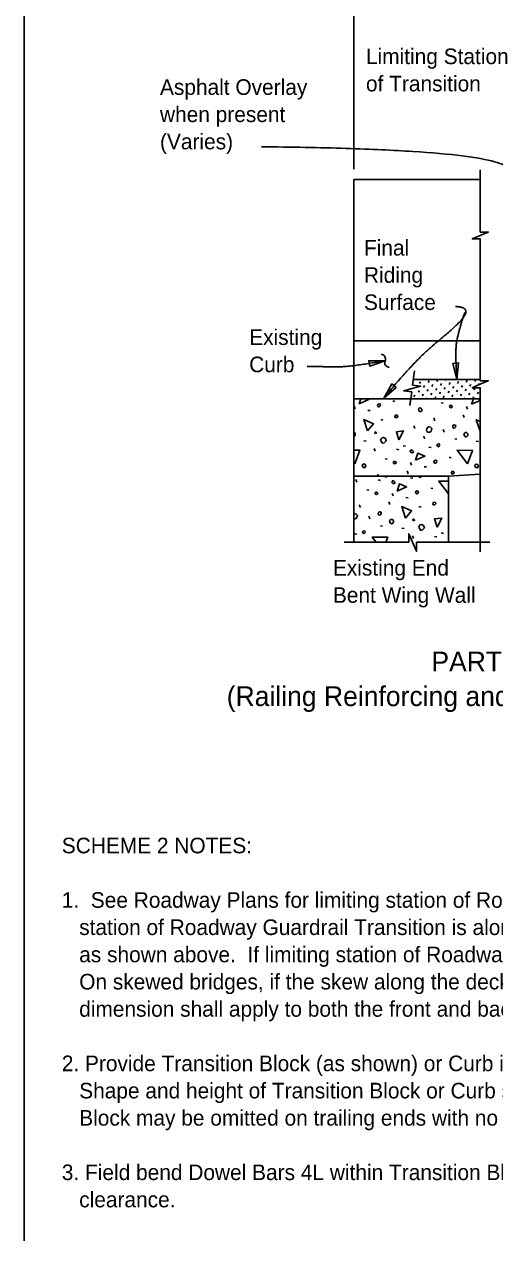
# Model space of a CAD drawing. Extents: x 1 to 39.2, y 0 to 26.
# Drawn here: x 20.53 to 26.61, y 0 to 15.72 of the extents above; entities that cross this region are included whole.
import ezdxf

# ---------------------------------------------------------------- set-up
doc = ezdxf.new("R2010")
doc.units = 0
for name, color, linetype in [('Dimension', 7, 'Continuous'), ('Miscellaneous', 7, 'Continuous'), ('TrafBarrierConc', 7, 'Continuous')]:
    doc.layers.add(name, color=color, linetype=linetype)

msp = doc.modelspace()

# ---------------------------------------------------------------- linework, layer by layer
at = {"layer": 'Dimension'}
for p, q in [((20.533, 25.97), (20.533, 0)), ((24.79, 19.042), (24.789, 13.85))]:
    msp.add_line(p, q, dxfattribs=at)
for points in [[(26.42, 12.096), (26.42, 12.948), (26.317, 12.948), (26.42, 12.993), (26.524, 13.038), (26.42, 13.038), (26.42, 13.841)], [(26.42, 8.903), (26.42, 11.026), (26.317, 11.026), (26.42, 11.071), (26.524, 11.116), (26.42, 11.116), (26.42, 12.096)], [(25.513, 10.797), (25.536, 10.971), (25.433, 10.984), (25.542, 11.015), (25.65, 11.046), (25.548, 11.06), (25.572, 11.242)], [(26.545, 9.028), (25.598, 9.028), (25.598, 8.912), (25.498, 9.137), (25.498, 9.028), (24.665, 9.028)]]:
    msp.add_lwpolyline(points, dxfattribs=at)
for points in [[(25.193, 11.373), (24.981, 11.373), (24.993, 11.304)], [(26.12, 11.135), (26.14, 11.345), (26.069, 11.34)], [(25.174, 10.89), (25.333, 11.029), (25.278, 11.074)]]:
    msp.add_lwpolyline(points, close=True, dxfattribs=at)
for centre, start, end in [((25.138, 11.398), 336.0025, 87.7297), ((25.247, 11.35), 156.0025, 267.7297)]:
    msp.add_arc(centre, 0.0596, start, end, dxfattribs=at)
for points in [[(23.597, 14.141), (26.772, 14.106), (26.847, 13.542), (26.922, 12.078), (27.461, 11.132)], [(26.101, 12.075), (26.22, 12.069), (26.245, 11.981), (26.101, 11.812), (25.569, 11.373), (25.174, 10.89)], [(26.221, 11.999), (26.114, 11.68), (26.101, 11.386), (26.12, 11.135)], [(24.184, 11.298), (24.459, 11.298), (24.71, 11.292), (25.193, 11.373)]]:
    msp.add_open_spline(points, degree=2, dxfattribs=at)
at = {"layer": 'Miscellaneous'}
for p, q in [((25.588, 11.127), (25.592, 11.133)), ((25.637, 11.079), (25.65, 11.101)), ((25.686, 11.03), (25.699, 11.052)), ((25.748, 11.092), (25.761, 11.114)), ((25.797, 11.043), (25.81, 11.065)), ((25.846, 10.994), (25.859, 11.016)), ((25.859, 11.104), (25.872, 11.127)), ((25.907, 11.056), (25.92, 11.078)), ((25.956, 11.007), (25.969, 11.029)), ((25.969, 11.117), (25.978, 11.133)), ((26.018, 11.069), (26.031, 11.091)), ((26.067, 11.02), (26.08, 11.042)), ((26.08, 11.13), (26.081, 11.133)), ((26.129, 11.082), (26.142, 11.104)), ((26.177, 11.033), (26.19, 11.055)), ((26.226, 10.984), (26.239, 11.006)), ((26.239, 11.095), (26.252, 11.117)), ((26.288, 11.046), (26.301, 11.068)), ((26.337, 10.997), (26.35, 11.019)), ((26.35, 11.107), (26.363, 11.13)), ((26.399, 11.059), (26.412, 11.081)), ((25.292, 10.855), (25.318, 10.849)), ((25.563, 10.906), (25.575, 10.929)), ((25.624, 10.968), (25.637, 10.99)), ((25.673, 10.919), (25.686, 10.941)), ((25.728, 10.88), (25.735, 10.893)), ((25.735, 10.981), (25.748, 11.003)), ((25.784, 10.932), (25.797, 10.954)), ((25.833, 10.883), (25.846, 10.906)), ((25.894, 10.945), (25.907, 10.967)), ((25.943, 10.896), (25.956, 10.919)), ((26.005, 10.958), (26.018, 10.98)), ((26.054, 10.909), (26.067, 10.932)), ((26.116, 10.971), (26.129, 10.993)), ((26.165, 10.922), (26.177, 10.944)), ((26.217, 10.88), (26.226, 10.896)), ((26.275, 10.935), (26.288, 10.957)), ((26.324, 10.886), (26.337, 10.909)), ((26.386, 10.948), (26.399, 10.97)), ((24.804, 10.752), (24.791, 10.786)), ((24.968, 10.733), (25, 10.729)), ((25.917, 10.83), (25.944, 10.825)), ((26.257, 10.749), (26.244, 10.782)), ((25.136, 10.614), (25.164, 10.607)), ((25.834, 10.598), (25.82, 10.634)), ((26.214, 10.639), (26.2, 10.674)), ((25.578, 10.498), (25.564, 10.533)), ((25.703, 10.365), (25.691, 10.399)), ((25.956, 10.452), (25.942, 10.487)), ((24.917, 10.338), (24.947, 10.333)), ((25.065, 10.204), (25.053, 10.238)), ((25.339, 10.231), (25.368, 10.224)), ((25.426, 10.275), (25.454, 10.268)), ((25.756, 10.259), (25.787, 10.254)), ((26.094, 10.363), (26.119, 10.36)), ((26.37, 10.335), (26.4, 10.33)), ((25.193, 10.105), (25.219, 10.1)), ((26.02, 10.126), (26.046, 10.121)), ((25.106, 9.883), (25.095, 9.909)), ((25.49, 9.914), (25.475, 9.95)), ((25.532, 10.024), (25.52, 10.057)), ((25.696, 10.004), (25.728, 10.001)), ((24.829, 9.806), (24.816, 9.84)), ((25.103, 9.833), (25.131, 9.825)), ((25.189, 9.877), (25.218, 9.87)), ((25.52, 9.861), (25.55, 9.856)), ((25.864, 9.886), (25.876, 9.883)), ((24.956, 9.707), (24.982, 9.702)), ((25.295, 9.626), (25.283, 9.659)), ((25.46, 9.606), (25.492, 9.603)), ((25.783, 9.728), (25.81, 9.723)), ((24.873, 9.475), (24.859, 9.511)), ((25.253, 9.516), (25.239, 9.551)), ((25.628, 9.488), (25.656, 9.481)), ((24.995, 9.329), (24.981, 9.364)), ((24.795, 9.136), (24.825, 9.131)), ((25.133, 9.24), (25.157, 9.237)), ((25.408, 9.212), (25.439, 9.207)), ((25.918, 9.148), (25.946, 9.141)), ((25.557, 9.078), (25.545, 9.111)), ((25.831, 9.104), (25.859, 9.097))]:
    msp.add_line(p, q, dxfattribs=at)
for points in [[(24.857, 10.816), (24.877, 10.883)], [(24.947, 10.883), (24.979, 10.871), (24.857, 10.816)], [(26.31, 10.812), (26.332, 10.883)], [(26.42, 10.862), (26.31, 10.812)], [(26.392, 10.883), (26.42, 10.872)], [(25.104, 10.78), (25.111, 10.78), (25.125, 10.788), (25.131, 10.803), (25.129, 10.812), (25.115, 10.819), (25.097, 10.809), (25.094, 10.798), (25.097, 10.788), (25.104, 10.78)], [(25.626, 10.736), (25.634, 10.72), (25.656, 10.717), (25.665, 10.733), (25.668, 10.747), (25.659, 10.756), (25.643, 10.765), (25.627, 10.759), (25.622, 10.743), (25.626, 10.736)], [(26.025, 10.772), (26.045, 10.766), (26.057, 10.775), (26.059, 10.788), (26.055, 10.791), (26.041, 10.798), (26.029, 10.796), (26.027, 10.784), (26.025, 10.772)], [(24.965, 10.468), (24.917, 10.614), (25.042, 10.559), (24.965, 10.468)], [(25.323, 10.639), (25.345, 10.639), (25.355, 10.65), (25.35, 10.669), (25.327, 10.671), (25.323, 10.66), (25.318, 10.651), (25.323, 10.639), (25.32, 10.643)], [(26.066, 10.519), (26.075, 10.503), (26.094, 10.505), (26.103, 10.517), (26.105, 10.536), (26.092, 10.542), (26.084, 10.544), (26.073, 10.54), (26.069, 10.536), (26.066, 10.519)], [(26.418, 10.464), (26.37, 10.611), (26.421, 10.589)], [(24.79, 10.394), (24.8, 10.402), (24.807, 10.413), (24.807, 10.434), (24.791, 10.45), (24.79, 10.45)], [(25.064, 10.432), (25.083, 10.441), (25.076, 10.448), (25.064, 10.453), (25.058, 10.441), (25.064, 10.432)], [(25.134, 10.347), (25.157, 10.31), (25.18, 10.312), (25.189, 10.321), (25.208, 10.34), (25.196, 10.37), (25.171, 10.384), (25.154, 10.377), (25.14, 10.363), (25.134, 10.347)], [(25.371, 10.351), (25.338, 10.455), (25.431, 10.468), (25.371, 10.351)], [(25.732, 10.46), (25.755, 10.448), (25.785, 10.46), (25.797, 10.498), (25.779, 10.515), (25.756, 10.521), (25.746, 10.514), (25.733, 10.494), (25.725, 10.478), (25.732, 10.46)], [(26.211, 10.42), (26.221, 10.399), (26.239, 10.388), (26.253, 10.399), (26.26, 10.409), (26.26, 10.43), (26.244, 10.446), (26.225, 10.445), (26.216, 10.436), (26.211, 10.42)], [(26.421, 10.468), (26.418, 10.464)], [(25.528, 10.186), (25.541, 10.185), (25.553, 10.19), (25.557, 10.201), (25.551, 10.209), (25.541, 10.217), (25.528, 10.222), (25.521, 10.208), (25.518, 10.197), (25.528, 10.186)], [(25.868, 10.271), (25.878, 10.261), (25.889, 10.268), (25.896, 10.278), (25.893, 10.296), (25.884, 10.298), (25.871, 10.296), (25.861, 10.285), (25.868, 10.271)], [(24.79, 10.219), (24.867, 10.218), (24.802, 10.043)], [(25.3, 10.047), (25.32, 10.042), (25.332, 10.05), (25.334, 10.063), (25.33, 10.066), (25.316, 10.073), (25.304, 10.072), (25.302, 10.059), (25.3, 10.047)], [(25.585, 10.087), (25.613, 10.179), (25.707, 10.142), (25.585, 10.087)], [(25.832, 10.052), (25.84, 10.052), (25.854, 10.059), (25.859, 10.075), (25.857, 10.084), (25.843, 10.091), (25.825, 10.08), (25.822, 10.07), (25.825, 10.059), (25.832, 10.052)], [(26.255, 10.04), (26.121, 10.217), (26.32, 10.215), (26.255, 10.04)], [(24.802, 10.043), (24.79, 10.06)], [(24.901, 10.011), (24.91, 9.996), (24.931, 9.992), (24.94, 10.008), (24.943, 10.022), (24.934, 10.031), (24.919, 10.04), (24.903, 10.034), (24.897, 10.019), (24.901, 10.011)], [(26.052, 9.911), (26.073, 9.911), (26.084, 9.921), (26.078, 9.941), (26.055, 9.943), (26.052, 9.932), (26.046, 9.923), (26.052, 9.911), (26.048, 9.914)], [(26.354, 10.008), (26.363, 9.992), (26.384, 9.988), (26.393, 10.004), (26.396, 10.019), (26.388, 10.027), (26.372, 10.036), (26.356, 10.031), (26.35, 10.015), (26.354, 10.008)], [(25.292, 9.788), (25.304, 9.787), (25.317, 9.792), (25.32, 9.802), (25.315, 9.811), (25.304, 9.818), (25.292, 9.824), (25.285, 9.81), (25.281, 9.799), (25.292, 9.788)], [(25.348, 9.689), (25.377, 9.781), (25.47, 9.744), (25.348, 9.689)], [(25.626, 9.883), (25.631, 9.873)], [(25.631, 9.873), (25.642, 9.863), (25.652, 9.87), (25.659, 9.88), (25.659, 9.883)], [(25.646, 9.883), (25.645, 9.886), (25.652, 9.883)], [(26.01, 9.653), (25.884, 9.818), (26.01, 9.817)], [(25.064, 9.649), (25.083, 9.643), (25.096, 9.652), (25.097, 9.665), (25.094, 9.668), (25.08, 9.675), (25.067, 9.673), (25.066, 9.661), (25.064, 9.649)], [(25.596, 9.654), (25.603, 9.654), (25.617, 9.661), (25.622, 9.677), (25.621, 9.686), (25.606, 9.693), (25.589, 9.682), (25.585, 9.672), (25.589, 9.661), (25.596, 9.654)], [(25.456, 9.341), (25.408, 9.488), (25.534, 9.433), (25.456, 9.341)], [(25.815, 9.513), (25.836, 9.513), (25.847, 9.523), (25.842, 9.543), (25.819, 9.544), (25.815, 9.534), (25.81, 9.525), (25.815, 9.513), (25.812, 9.516)], [(24.79, 9.327), (24.793, 9.325), (24.823, 9.338), (24.836, 9.375), (24.818, 9.392), (24.795, 9.398), (24.79, 9.394)], [(25.104, 9.396), (25.113, 9.38), (25.133, 9.382), (25.142, 9.394), (25.143, 9.414), (25.131, 9.419), (25.122, 9.421), (25.111, 9.417), (25.108, 9.414), (25.104, 9.396)], [(25.249, 9.297), (25.26, 9.276), (25.278, 9.265), (25.292, 9.276), (25.299, 9.286), (25.299, 9.308), (25.283, 9.323), (25.264, 9.322), (25.255, 9.313), (25.249, 9.297)], [(25.555, 9.306), (25.575, 9.315), (25.568, 9.322), (25.555, 9.327), (25.55, 9.315), (25.555, 9.306)], [(25.863, 9.224), (25.829, 9.329), (25.923, 9.341), (25.863, 9.224)], [(24.906, 9.148), (24.917, 9.138), (24.928, 9.145), (24.935, 9.155), (24.931, 9.173), (24.922, 9.175), (24.91, 9.173), (24.899, 9.163), (24.906, 9.148)], [(25.626, 9.221), (25.649, 9.184), (25.672, 9.186), (25.681, 9.194), (25.7, 9.214), (25.688, 9.244), (25.663, 9.258), (25.645, 9.251), (25.631, 9.237), (25.626, 9.221)], [(25.076, 9.028), (25.026, 9.094), (25.226, 9.092), (25.202, 9.028)]]:
    msp.add_lwpolyline(points, dxfattribs=at)
at = {"layer": 'TrafBarrierConc'}
for p, q in [((24.789, 13.716), (24.789, 11.633)), ((26.42, 13.716), (24.789, 13.716)), ((24.789, 11.633), (26.42, 11.633)), ((24.79, 11.633), (24.79, 9.028)), ((25.558, 11.133), (26.42, 11.133)), ((24.789, 10.883), (26.42, 10.883)), ((26.01, 9.883), (26.421, 9.909)), ((26.01, 9.883), (24.79, 9.883)), ((26.01, 9.883), (26.01, 9.028))]:
    msp.add_line(p, q, dxfattribs=at)

# ---------------------------------------------------------------- texts
at = {"layer": 'Dimension'}
for s, height, p in [('Limiting Station', 0.2016, (24.945, 15.208)), ('Asphalt Overlay ', 0.2016, (22.285, 14.811)), ('of Transition', 0.2016, (24.945, 14.856)), ('when present', 0.2016, (22.285, 14.459)), ('(Varies)', 0.2016, (22.285, 14.107)), ('Final ', 0.2016, (24.919, 12.734)), ('Riding ', 0.2016, (24.919, 12.382)), ('Surface', 0.2016, (24.919, 12.03)), ('Existing ', 0.2016, (23.437, 11.578)), ('Curb', 0.2016, (23.437, 11.226)), ('Existing End ', 0.2016, (24.518, 8.597)), ('Bent Wing Wall', 0.2016, (24.518, 8.245)), ('PARTIAL ELEVATION OF INSIDE FACE OF RAILING', 0.256, (25.79, 7.358)), ('(Railing Reinforcing and Expansion Dowel Assemblies not shown for clarity)', 0.256, (23.147, 6.91)), ('SCHEME 2 NOTES:', 0.2016, (21.017, 5.007)), ('1.  See Roadway Plans for limiting station of Roadway Guardrail Transition or other site specific treatment.  If limiting ', 0.2016, (21.017, 4.303)), ('   station of Roadway Guardrail Transition is along the Wing Wall, attach Thrie-Beam Terminal Connector to railing ', 0.2016, (21.017, 3.951)), ('   as shown above.  If limiting station of Roadway Guardrail Transition is on the bridge, see Index 521-481, Sheet 1.  ', 0.2016, (21.017, 3.599)), ('   On skewed bridges, if the skew along the deck joint extends across the width of the railing, the 2\'-6" minimum ', 0.2016, (21.017, 3.247)), ('   dimension shall apply to both the front and back face of the railing. ', 0.2016, (21.017, 2.895)), ('2. Provide Transition Block (as shown) or Curb if existing Approach Slab does not have a curb, see Roadway Plans.  ', 0.2016, (21.017, 2.191)), ('   Shape and height of Transition Block or Curb shall match existing bridge curb.  Railing End Transition and Transition ', 0.2016, (21.017, 1.839)), ('   Block may be omitted on trailing ends with no opposing traffic.', 0.2016, (21.017, 1.487)), ('3. Field bend Dowel Bars 4L within Transition Block as required to maintain 2" top and side clearance and 3" bottom ', 0.2016, (21.017, 0.783)), ('   clearance.', 0.2016, (21.017, 0.431))]:
    msp.add_text(s, height=height, dxfattribs=at).set_placement(p)

doc.saveas('drawing.dxf')
